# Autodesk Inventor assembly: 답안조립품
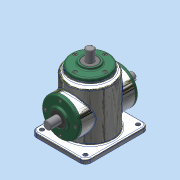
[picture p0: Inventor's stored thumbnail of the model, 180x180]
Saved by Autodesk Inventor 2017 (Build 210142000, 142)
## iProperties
Part Number: 답안조립품
Material: 일반
Document SubType Name: Assembly
Designer: MRC
Author: MRC
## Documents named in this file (16)
- C:\Users\MRC\Desktop\710116V1010\답안조립품.iam
- C:\Users\MRC\Desktop\710116V1010\본체.ipt
- C:\Users\MRC\Desktop\710116V1010\메인 베벨기어.ipt
- C:\Users\MRC\Desktop\710116V1010\메인 축.ipt
- 메인 축.ipt
- C:\Users\MRC\Desktop\710116V1010\베어링 6203.ipt
- C:\Users\MRC\Desktop\710116V1010\볼트 M4.ipt
- 볼트 M4.ipt
- C:\Users\MRC\Desktop\710116V1010\서브 베벨기어.ipt
- C:\Users\MRC\Desktop\710116V1010\서브 축.ipt
- 서브 축.ipt
- C:\Users\MRC\Desktop\710116V1010\오일 실.ipt
- 오일 실.ipt
- C:\Users\MRC\Desktop\710116V1010\커버.ipt
- C:\Users\MRC\Desktop\710116V1010\키 4x4.ipt
- C:\Users\MRC\Desktop\710116V1010\키 5x5.ipt
